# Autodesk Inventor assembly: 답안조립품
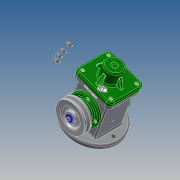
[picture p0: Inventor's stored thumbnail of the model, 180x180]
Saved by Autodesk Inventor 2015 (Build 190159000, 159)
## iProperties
Created: 2018-10
Part Number: 답안조립품
Document SubType Name: Assembly
Designer: user
Author: user
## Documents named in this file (18)
- C:\Users\user\Desktop\481007V1048\답안조립품.iam
- C:\Users\user\Desktop\481007V1048\본체.ipt
- C:\Users\user\Desktop\481007V1048\E-링.ipt
- C:\Users\user\Desktop\481007V1048\V-벨트풀리.ipt
- C:\Users\user\Desktop\481007V1048\덮개.ipt
- C:\Users\user\Desktop\481007V1048\뒤커버.ipt
- C:\Users\user\Desktop\481007V1048\링크.ipt
- C:\Users\user\Desktop\481007V1048\베어링 17 x 40 x 12.ipt
- C:\Users\user\Desktop\481007V1048\볼트 M4 x 8.ipt
- C:\Users\user\Desktop\481007V1048\볼트 M4 x 10.ipt
- C:\Users\user\Desktop\481007V1048\슬라이더.ipt
- C:\Users\user\Desktop\481007V1048\앞커버.ipt
- C:\Users\user\Desktop\481007V1048\오일 실 17 30 8.ipt
- C:\Users\user\Desktop\481007V1048\와셔 4x16.ipt
- C:\Users\user\Desktop\481007V1048\클레비스 핀 6 x 22.ipt
- 클레비스 핀 6 x 22.ipt
- C:\Users\user\Desktop\481007V1048\키 4 x 4 x 12.ipt
- C:\Users\user\Desktop\481007V1048\편심축.ipt
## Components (2 placed, 2 different names)
1. E-링:1
2. V-벨트풀리:1
